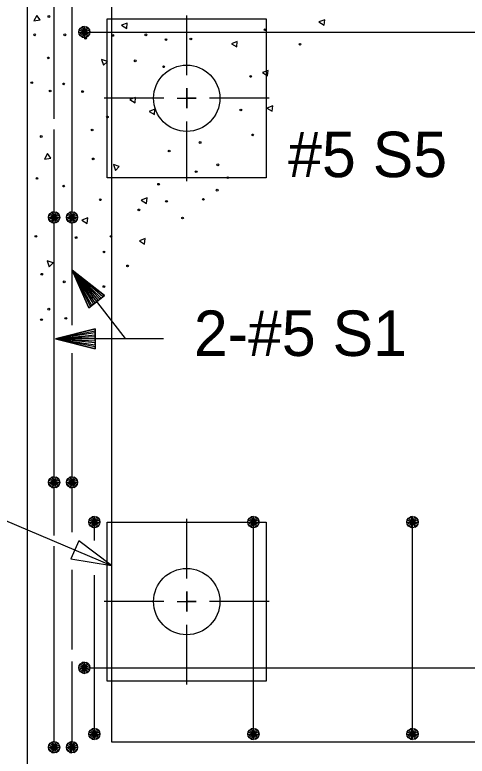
# Model space of a CAD drawing. Extents: x -408 to -23, y -15 to 117.
# Drawn here: x -95.399 to -93.977, y 60.275 to 62.607 of the extents above; entities that cross this region are included whole.
import ezdxf

# ---------------------------------------------------------------- set-up
doc = ezdxf.new("R2010")
doc.units = 0
for name, color, linetype in [('Arrowhead Terminators CELL', 7, 'Continuous'), ('Dimension Lines', 7, 'Continuous'), ('Rebar Lines', 7, 'Continuous'), ('Sup Concrete Girder Lines', 7, 'Continuous'), ('Sup Cored Slab Unit', 7, 'Continuous'), ('Text', 7, 'Continuous'), ('User Information Notes', 7, 'Continuous')]:
    doc.layers.add(name, color=color, linetype=linetype)

msp = doc.modelspace()

# ---------------------------------------------------------------- linework, layer by layer
at = {"layer": 'Arrowhead Terminators CELL'}
msp.add_lwpolyline([(-95.0954, 60.8754), (-95.1983, 60.953), (-95.2227, 60.8954)], close=True, dxfattribs=at)
at = {"layer": 'Dimension Lines'}
for p, q in [((-94.859, 62.4179), (-94.859, 62.6054)), ((-94.9305, 62.3448), (-95.118, 62.3448)), ((-94.5999, 62.3448), (-94.7874, 62.3448)), ((-94.859, 62.0843), (-94.859, 62.2718)), ((-95.0526, 61.5882), (-95.2719, 61.5882)), ((-94.859, 60.8345), (-94.859, 61.022)), ((-94.9305, 60.7615), (-95.118, 60.7615)), ((-94.5999, 60.7615), (-94.7874, 60.7615)), ((-94.859, 60.501), (-94.859, 60.6885))]:
    msp.add_line(p, q, dxfattribs=at)
for points in [[(-94.8889, 62.3448), (-94.859, 62.3448), (-94.8291, 62.3448), (-94.859, 62.3448), (-94.859, 62.3762), (-94.859, 62.3448), (-94.859, 62.3135), (-94.859, 62.3448)], [(-95.2189, 61.8035), (-95.0522, 61.589), (-94.9315, 61.589)], [(-95.1422, 61.7048), (-95.1471, 61.7009), (-95.2189, 61.8035), (-95.152, 61.6971), (-95.157, 61.6933), (-95.2189, 61.8035), (-95.1619, 61.6894), (-95.1668, 61.6856), (-95.2189, 61.8035), (-95.1175, 61.724), (-95.1225, 61.7201), (-95.2189, 61.8035), (-95.1274, 61.7163), (-95.1323, 61.7124), (-95.2189, 61.8035), (-95.1372, 61.7086), (-95.1668, 61.6856), (-95.1175, 61.724), (-95.2189, 61.8035), (-95.1668, 61.6856)], [(-95.1469, 61.5882), (-95.1469, 61.5945), (-95.2719, 61.5882), (-95.1469, 61.6007), (-95.1469, 61.607), (-95.2719, 61.5882), (-95.1469, 61.6132), (-95.1469, 61.6195), (-95.2719, 61.5882), (-95.1469, 61.557), (-95.1469, 61.5632), (-95.2719, 61.5882), (-95.1469, 61.5695), (-95.1469, 61.5757), (-95.2719, 61.5882), (-95.1469, 61.582), (-95.1469, 61.6195), (-95.1469, 61.557), (-95.2719, 61.5882), (-95.1469, 61.6195)], [(-96.0286, 61.1762), (-95.8052, 61.1762), (-95.0954, 60.8754)], [(-94.8889, 60.7615), (-94.859, 60.7615), (-94.8291, 60.7615), (-94.859, 60.7615), (-94.859, 60.7929), (-94.859, 60.7615), (-94.859, 60.7302), (-94.859, 60.7615)]]:
    msp.add_lwpolyline(points, dxfattribs=at)
at = {"layer": 'Rebar Lines'}
for p, q in [((-95.2757, 62.28), (-95.2757, 62.8032)), ((-95.2195, 61.6311), (-95.2195, 62.6541)), ((-95.1806, 62.5532), (-92.5556, 62.5532)), ((-95.2757, 61.43), (-95.2757, 62.2463)), ((-95.2195, 60.9796), (-95.2195, 61.543)), ((-95.2757, 60.9693), (-95.2757, 61.43)), ((-95.1492, 60.9535), (-95.1492, 61.0115)), ((-94.6492, 60.3448), (-94.6492, 61.0115)), ((-94.1492, 60.3448), (-94.1492, 61.0115)), ((-95.2757, 60.3032), (-95.2757, 60.9356)), ((-95.2195, 60.611), (-95.2195, 60.8609)), ((-95.1492, 60.3448), (-95.1492, 60.8443)), ((-95.2195, 60.3032), (-95.2195, 60.5731)), ((-95.1806, 60.5532), (-92.5556, 60.5532))]:
    msp.add_line(p, q, dxfattribs=at)
for points in [[(-93.637, 62.7867), (-95.0954, 62.7867), (-95.0954, 60.3201), (-93.637, 60.3201)], [(-95.1982, 62.5532), (-95.1969, 62.5599), (-95.1931, 62.5656), (-95.1874, 62.5695), (-95.1806, 62.5708), (-95.1739, 62.5695), (-95.1682, 62.5656), (-95.1644, 62.5599), (-95.163, 62.5532), (-95.1644, 62.5465), (-95.1682, 62.5407), (-95.1739, 62.5369), (-95.1806, 62.5355), (-95.1874, 62.5369), (-95.1931, 62.5407), (-95.1969, 62.5464), (-95.1982, 62.5532), (-95.1806, 62.5532), (-95.163, 62.5532), (-95.1644, 62.5599), (-95.1806, 62.5532), (-95.1682, 62.5656), (-95.1739, 62.5695), (-95.1806, 62.5532), (-95.1806, 62.5708), (-95.1874, 62.5695), (-95.1806, 62.5532), (-95.1931, 62.5656), (-95.1969, 62.5599), (-95.1806, 62.5532), (-95.1969, 62.5464), (-95.1931, 62.5407), (-95.1806, 62.5532), (-95.1874, 62.5369), (-95.1806, 62.5355), (-95.1806, 62.5532), (-95.1739, 62.5369), (-95.1682, 62.5407), (-95.1806, 62.5532), (-95.1644, 62.5465)], [(-95.2933, 61.9698), (-95.292, 61.9766), (-95.2882, 61.9823), (-95.2825, 61.9861), (-95.2757, 61.9874), (-95.269, 61.9861), (-95.2632, 61.9823), (-95.2594, 61.9766), (-95.2581, 61.9698), (-95.2594, 61.9631), (-95.2632, 61.9574), (-95.2689, 61.9535), (-95.2757, 61.9522), (-95.2825, 61.9535), (-95.2881, 61.9573), (-95.292, 61.9631), (-95.2933, 61.9698), (-95.2757, 61.9698), (-95.2581, 61.9698), (-95.2594, 61.9766), (-95.2757, 61.9698), (-95.2632, 61.9823), (-95.269, 61.9861), (-95.2757, 61.9698), (-95.2757, 61.9874), (-95.2825, 61.9861), (-95.2757, 61.9698), (-95.2882, 61.9823), (-95.292, 61.9766), (-95.2757, 61.9698), (-95.292, 61.9631), (-95.2881, 61.9573), (-95.2757, 61.9698), (-95.2825, 61.9535), (-95.2757, 61.9522), (-95.2757, 61.9698), (-95.2689, 61.9535), (-95.2632, 61.9574), (-95.2757, 61.9698), (-95.2594, 61.9631)], [(-95.2371, 61.9698), (-95.2358, 61.9766), (-95.232, 61.9823), (-95.2263, 61.9861), (-95.2195, 61.9874), (-95.2128, 61.9861), (-95.2071, 61.9823), (-95.2033, 61.9766), (-95.2019, 61.9698), (-95.2033, 61.9631), (-95.2071, 61.9574), (-95.2128, 61.9535), (-95.2195, 61.9522), (-95.2263, 61.9535), (-95.232, 61.9573), (-95.2358, 61.9631), (-95.2371, 61.9698), (-95.2195, 61.9698), (-95.2019, 61.9698), (-95.2033, 61.9766), (-95.2195, 61.9698), (-95.2071, 61.9823), (-95.2128, 61.9861), (-95.2195, 61.9698), (-95.2195, 61.9874), (-95.2263, 61.9861), (-95.2195, 61.9698), (-95.232, 61.9823), (-95.2358, 61.9766), (-95.2195, 61.9698), (-95.2358, 61.9631), (-95.232, 61.9573), (-95.2195, 61.9698), (-95.2263, 61.9535), (-95.2195, 61.9522), (-95.2195, 61.9698), (-95.2128, 61.9535), (-95.2071, 61.9574), (-95.2195, 61.9698), (-95.2033, 61.9631)], [(-95.2933, 61.1365), (-95.292, 61.1432), (-95.2882, 61.149), (-95.2825, 61.1528), (-95.2757, 61.1541), (-95.269, 61.1528), (-95.2632, 61.149), (-95.2594, 61.1433), (-95.2581, 61.1365), (-95.2594, 61.1298), (-95.2632, 61.1241), (-95.2689, 61.1202), (-95.2757, 61.1189), (-95.2825, 61.1202), (-95.2881, 61.124), (-95.292, 61.1297), (-95.2933, 61.1365), (-95.2757, 61.1365), (-95.2581, 61.1365), (-95.2594, 61.1433), (-95.2757, 61.1365), (-95.2632, 61.149), (-95.269, 61.1528), (-95.2757, 61.1365), (-95.2757, 61.1541), (-95.2825, 61.1528), (-95.2757, 61.1365), (-95.2882, 61.149), (-95.292, 61.1432), (-95.2757, 61.1365), (-95.292, 61.1297), (-95.2881, 61.124), (-95.2757, 61.1365), (-95.2825, 61.1202), (-95.2757, 61.1189), (-95.2757, 61.1365), (-95.2689, 61.1202), (-95.2632, 61.1241), (-95.2757, 61.1365), (-95.2594, 61.1298)], [(-95.2371, 61.1365), (-95.2358, 61.1432), (-95.232, 61.149), (-95.2263, 61.1528), (-95.2195, 61.1541), (-95.2128, 61.1528), (-95.2071, 61.149), (-95.2033, 61.1433), (-95.2019, 61.1365), (-95.2033, 61.1298), (-95.2071, 61.1241), (-95.2128, 61.1202), (-95.2195, 61.1189), (-95.2263, 61.1202), (-95.232, 61.124), (-95.2358, 61.1297), (-95.2371, 61.1365), (-95.2195, 61.1365), (-95.2019, 61.1365), (-95.2033, 61.1433), (-95.2195, 61.1365), (-95.2071, 61.149), (-95.2128, 61.1528), (-95.2195, 61.1365), (-95.2195, 61.1541), (-95.2263, 61.1528), (-95.2195, 61.1365), (-95.232, 61.149), (-95.2358, 61.1432), (-95.2195, 61.1365), (-95.2358, 61.1297), (-95.232, 61.124), (-95.2195, 61.1365), (-95.2263, 61.1202), (-95.2195, 61.1189), (-95.2195, 61.1365), (-95.2128, 61.1202), (-95.2071, 61.1241), (-95.2195, 61.1365), (-95.2033, 61.1298)], [(-95.1668, 61.0115), (-95.1655, 61.0182), (-95.1617, 61.0239), (-95.1559, 61.0278), (-95.1492, 61.0291), (-95.1425, 61.0278), (-95.1367, 61.0239), (-95.1329, 61.0182), (-95.1316, 61.0115), (-95.1329, 61.0047), (-95.1367, 60.999), (-95.1424, 60.9952), (-95.1492, 60.9938), (-95.1559, 60.9952), (-95.1616, 60.999), (-95.1655, 61.0047), (-95.1668, 61.0115), (-95.1492, 61.0115), (-95.1316, 61.0115), (-95.1329, 61.0182), (-95.1492, 61.0115), (-95.1367, 61.0239), (-95.1425, 61.0278), (-95.1492, 61.0115), (-95.1492, 61.0291), (-95.1559, 61.0278), (-95.1492, 61.0115), (-95.1617, 61.0239), (-95.1655, 61.0182), (-95.1492, 61.0115), (-95.1655, 61.0047), (-95.1616, 60.999), (-95.1492, 61.0115), (-95.1559, 60.9952), (-95.1492, 60.9938), (-95.1492, 61.0115), (-95.1424, 60.9952), (-95.1367, 60.999), (-95.1492, 61.0115), (-95.1329, 61.0047)], [(-94.6668, 61.0115), (-94.6655, 61.0182), (-94.6617, 61.0239), (-94.6559, 61.0278), (-94.6492, 61.0291), (-94.6425, 61.0278), (-94.6367, 61.0239), (-94.6329, 61.0182), (-94.6316, 61.0115), (-94.6329, 61.0047), (-94.6367, 60.999), (-94.6424, 60.9952), (-94.6492, 60.9938), (-94.6559, 60.9952), (-94.6616, 60.999), (-94.6655, 61.0047), (-94.6668, 61.0115), (-94.6492, 61.0115), (-94.6316, 61.0115), (-94.6329, 61.0182), (-94.6492, 61.0115), (-94.6367, 61.0239), (-94.6425, 61.0278), (-94.6492, 61.0115), (-94.6492, 61.0291), (-94.6559, 61.0278), (-94.6492, 61.0115), (-94.6617, 61.0239), (-94.6655, 61.0182), (-94.6492, 61.0115), (-94.6655, 61.0047), (-94.6616, 60.999), (-94.6492, 61.0115), (-94.6559, 60.9952), (-94.6492, 60.9938), (-94.6492, 61.0115), (-94.6424, 60.9952), (-94.6367, 60.999), (-94.6492, 61.0115), (-94.6329, 61.0047)], [(-94.1668, 61.0115), (-94.1655, 61.0182), (-94.1617, 61.0239), (-94.1559, 61.0278), (-94.1492, 61.0291), (-94.1425, 61.0278), (-94.1367, 61.0239), (-94.1329, 61.0182), (-94.1316, 61.0115), (-94.1329, 61.0047), (-94.1367, 60.999), (-94.1424, 60.9952), (-94.1492, 60.9938), (-94.1559, 60.9952), (-94.1616, 60.999), (-94.1655, 61.0047), (-94.1668, 61.0115), (-94.1492, 61.0115), (-94.1316, 61.0115), (-94.1329, 61.0182), (-94.1492, 61.0115), (-94.1367, 61.0239), (-94.1425, 61.0278), (-94.1492, 61.0115), (-94.1492, 61.0291), (-94.1559, 61.0278), (-94.1492, 61.0115), (-94.1617, 61.0239), (-94.1655, 61.0182), (-94.1492, 61.0115), (-94.1655, 61.0047), (-94.1616, 60.999), (-94.1492, 61.0115), (-94.1559, 60.9952), (-94.1492, 60.9938), (-94.1492, 61.0115), (-94.1424, 60.9952), (-94.1367, 60.999), (-94.1492, 61.0115), (-94.1329, 61.0047)], [(-95.1982, 60.5532), (-95.1969, 60.5599), (-95.1931, 60.5656), (-95.1874, 60.5695), (-95.1806, 60.5708), (-95.1739, 60.5695), (-95.1682, 60.5656), (-95.1644, 60.5599), (-95.163, 60.5532), (-95.1644, 60.5465), (-95.1682, 60.5407), (-95.1739, 60.5369), (-95.1806, 60.5355), (-95.1874, 60.5369), (-95.1931, 60.5407), (-95.1969, 60.5464), (-95.1982, 60.5532), (-95.1806, 60.5532), (-95.163, 60.5532), (-95.1644, 60.5599), (-95.1806, 60.5532), (-95.1682, 60.5656), (-95.1739, 60.5695), (-95.1806, 60.5532), (-95.1806, 60.5708), (-95.1874, 60.5695), (-95.1806, 60.5532), (-95.1931, 60.5656), (-95.1969, 60.5599), (-95.1806, 60.5532), (-95.1969, 60.5464), (-95.1931, 60.5407), (-95.1806, 60.5532), (-95.1874, 60.5369), (-95.1806, 60.5355), (-95.1806, 60.5532), (-95.1739, 60.5369), (-95.1682, 60.5407), (-95.1806, 60.5532), (-95.1644, 60.5465)], [(-95.1668, 60.3448), (-95.1655, 60.3515), (-95.1617, 60.3572), (-95.1559, 60.3611), (-95.1492, 60.3624), (-95.1425, 60.3611), (-95.1367, 60.3572), (-95.1329, 60.3516), (-95.1316, 60.3448), (-95.1329, 60.3381), (-95.1367, 60.3323), (-95.1424, 60.3285), (-95.1492, 60.3271), (-95.1559, 60.3285), (-95.1616, 60.3323), (-95.1655, 60.338), (-95.1668, 60.3448), (-95.1492, 60.3448), (-95.1316, 60.3448), (-95.1329, 60.3516), (-95.1492, 60.3448), (-95.1367, 60.3572), (-95.1425, 60.3611), (-95.1492, 60.3448), (-95.1492, 60.3624), (-95.1559, 60.3611), (-95.1492, 60.3448), (-95.1617, 60.3572), (-95.1655, 60.3515), (-95.1492, 60.3448), (-95.1655, 60.338), (-95.1616, 60.3323), (-95.1492, 60.3448), (-95.1559, 60.3285), (-95.1492, 60.3271), (-95.1492, 60.3448), (-95.1424, 60.3285), (-95.1367, 60.3323), (-95.1492, 60.3448), (-95.1329, 60.3381)], [(-94.6668, 60.3448), (-94.6655, 60.3515), (-94.6617, 60.3572), (-94.6559, 60.3611), (-94.6492, 60.3624), (-94.6425, 60.3611), (-94.6367, 60.3572), (-94.6329, 60.3516), (-94.6316, 60.3448), (-94.6329, 60.3381), (-94.6367, 60.3323), (-94.6424, 60.3285), (-94.6492, 60.3271), (-94.6559, 60.3285), (-94.6616, 60.3323), (-94.6655, 60.338), (-94.6668, 60.3448), (-94.6492, 60.3448), (-94.6316, 60.3448), (-94.6329, 60.3516), (-94.6492, 60.3448), (-94.6367, 60.3572), (-94.6425, 60.3611), (-94.6492, 60.3448), (-94.6492, 60.3624), (-94.6559, 60.3611), (-94.6492, 60.3448), (-94.6617, 60.3572), (-94.6655, 60.3515), (-94.6492, 60.3448), (-94.6655, 60.338), (-94.6616, 60.3323), (-94.6492, 60.3448), (-94.6559, 60.3285), (-94.6492, 60.3271), (-94.6492, 60.3448), (-94.6424, 60.3285), (-94.6367, 60.3323), (-94.6492, 60.3448), (-94.6329, 60.3381)], [(-94.1668, 60.3448), (-94.1655, 60.3515), (-94.1617, 60.3572), (-94.1559, 60.3611), (-94.1492, 60.3624), (-94.1425, 60.3611), (-94.1367, 60.3572), (-94.1329, 60.3516), (-94.1316, 60.3448), (-94.1329, 60.3381), (-94.1367, 60.3323), (-94.1424, 60.3285), (-94.1492, 60.3271), (-94.1559, 60.3285), (-94.1616, 60.3323), (-94.1655, 60.338), (-94.1668, 60.3448), (-94.1492, 60.3448), (-94.1316, 60.3448), (-94.1329, 60.3516), (-94.1492, 60.3448), (-94.1367, 60.3572), (-94.1425, 60.3611), (-94.1492, 60.3448), (-94.1492, 60.3624), (-94.1559, 60.3611), (-94.1492, 60.3448), (-94.1617, 60.3572), (-94.1655, 60.3515), (-94.1492, 60.3448), (-94.1655, 60.338), (-94.1616, 60.3323), (-94.1492, 60.3448), (-94.1559, 60.3285), (-94.1492, 60.3271), (-94.1492, 60.3448), (-94.1424, 60.3285), (-94.1367, 60.3323), (-94.1492, 60.3448), (-94.1329, 60.3381)], [(-95.2933, 60.3032), (-95.292, 60.3099), (-95.2882, 60.3156), (-95.2825, 60.3195), (-95.2757, 60.3208), (-95.269, 60.3195), (-95.2632, 60.3156), (-95.2594, 60.3099), (-95.2581, 60.3032), (-95.2594, 60.2965), (-95.2632, 60.2907), (-95.2689, 60.2869), (-95.2757, 60.2855), (-95.2825, 60.2869), (-95.2881, 60.2907), (-95.292, 60.2964), (-95.2933, 60.3032), (-95.2757, 60.3032), (-95.2581, 60.3032), (-95.2594, 60.3099), (-95.2757, 60.3032), (-95.2632, 60.3156), (-95.269, 60.3195), (-95.2757, 60.3032), (-95.2757, 60.3208), (-95.2825, 60.3195), (-95.2757, 60.3032), (-95.2882, 60.3156), (-95.292, 60.3099), (-95.2757, 60.3032), (-95.292, 60.2964), (-95.2881, 60.2907), (-95.2757, 60.3032), (-95.2825, 60.2869), (-95.2757, 60.2855), (-95.2757, 60.3032), (-95.2689, 60.2869), (-95.2632, 60.2907), (-95.2757, 60.3032), (-95.2594, 60.2965)], [(-95.2372, 60.3032), (-95.2359, 60.3099), (-95.2321, 60.3156), (-95.2264, 60.3195), (-95.2196, 60.3208), (-95.2129, 60.3195), (-95.2072, 60.3156), (-95.2034, 60.3099), (-95.202, 60.3032), (-95.2034, 60.2965), (-95.2072, 60.2907), (-95.2129, 60.2869), (-95.2196, 60.2855), (-95.2264, 60.2869), (-95.2321, 60.2907), (-95.2359, 60.2964), (-95.2372, 60.3032), (-95.2196, 60.3032), (-95.202, 60.3032), (-95.2034, 60.3099), (-95.2196, 60.3032), (-95.2072, 60.3156), (-95.2129, 60.3195), (-95.2196, 60.3032), (-95.2196, 60.3208), (-95.2264, 60.3195), (-95.2196, 60.3032), (-95.2321, 60.3156), (-95.2359, 60.3099), (-95.2196, 60.3032), (-95.2359, 60.2964), (-95.2321, 60.2907), (-95.2196, 60.3032), (-95.2264, 60.2869), (-95.2196, 60.2855), (-95.2196, 60.3032), (-95.2129, 60.2869), (-95.2072, 60.2907), (-95.2196, 60.3032), (-95.2034, 60.2965)]]:
    msp.add_lwpolyline(points, dxfattribs=at)
at = {"layer": 'Sup Concrete Girder Lines'}
msp.add_line((-95.359, 60.0532), (-95.359, 63.0532), dxfattribs=at)
for points in [[(-95.3198, 62.5914), (-95.3298, 62.6055), (-95.339, 62.5885), (-95.3198, 62.5914)], [(-95.0472, 62.5643), (-95.0457, 62.5815), (-95.0637, 62.5744), (-95.0472, 62.5643)], [(-94.4268, 62.5746), (-94.4253, 62.5918), (-94.4432, 62.5847), (-94.4268, 62.5746)], [(-94.7018, 62.5064), (-94.7003, 62.5235), (-94.7183, 62.5165), (-94.7018, 62.5064)], [(-95.1204, 62.4486), (-95.1081, 62.4608), (-95.1265, 62.4669), (-95.1204, 62.4486)], [(-94.6046, 62.4154), (-94.6031, 62.4325), (-94.6211, 62.4255), (-94.6046, 62.4154)], [(-95.0211, 62.3303), (-95.0196, 62.3475), (-95.0376, 62.3404), (-95.0211, 62.3303)], [(-94.5902, 62.3037), (-94.5887, 62.3209), (-94.6066, 62.3138), (-94.5902, 62.3037)], [(-94.9603, 62.2933), (-94.9588, 62.3105), (-94.9768, 62.3034), (-94.9603, 62.2933)], [(-95.2864, 62.1563), (-95.2964, 62.1705), (-95.3055, 62.1535), (-95.2864, 62.1563)], [(-95.0832, 62.1177), (-95.0709, 62.1299), (-95.0893, 62.136), (-95.0832, 62.1177)], [(-94.9852, 62.0142), (-94.9837, 62.0314), (-95.0016, 62.0243), (-94.9852, 62.0142)], [(-95.1717, 61.951), (-95.1702, 61.9682), (-95.1882, 61.9611), (-95.1717, 61.951)], [(-94.9914, 61.8859), (-94.9899, 61.9031), (-95.0078, 61.896), (-94.9914, 61.8859)], [(-95.2915, 61.8146), (-95.2792, 61.8269), (-95.2976, 61.833), (-95.2915, 61.8146)]]:
    msp.add_lwpolyline(points, dxfattribs=at)
for centre, radius in [((-95.2922, 62.602), 0.00273), ((-94.6123, 62.5602), 0.00273), ((-95.3368, 62.5443), 0.00273), ((-95.242, 62.5443), 0.00273), ((-95.1769, 62.5332), 0.00273), ((-95.0914, 62.5425), 0.00273), ((-94.9873, 62.5443), 0.00273), ((-94.9241, 62.5295), 0.00273), ((-94.846, 62.5313), 0.00273), ((-94.5027, 62.5147), 0.00273), ((-95.294, 62.4718), 0.00273), ((-95.0208, 62.4625), 0.00273), ((-94.859, 62.3448), 0.1042), ((-94.9315, 62.444), 0.00273), ((-94.6578, 62.4134), 0.00273), ((-95.3461, 62.3937), 0.00273), ((-95.2457, 62.39), 0.00273), ((-95.2885, 62.3677), 0.00273), ((-95.1862, 62.3658), 0.00273), ((-94.6888, 62.3079), 0.00273), ((-95.1081, 62.2859), 0.00273), ((-95.1565, 62.245), 0.00273), ((-95.3163, 62.2245), 0.00273), ((-94.6516, 62.2294), 0.00273), ((-94.817, 62.2057), 0.00273), ((-94.9142, 62.1788), 0.00273), ((-95.1528, 62.1539), 0.00273), ((-94.7612, 62.1354), 0.00273), ((-94.8292, 62.1139), 0.00273), ((-95.3294, 62.0925), 0.00273), ((-94.7302, 62.0949), 0.00273), ((-95.2457, 62.0684), 0.00273), ((-94.9473, 62.0743), 0.00273), ((-94.7632, 62.0556), 0.00273), ((-95.1305, 62.0256), 0.00273), ((-94.9225, 62.0205), 0.00273), ((-94.8067, 62.0267), 0.00273), ((-95.0093, 61.9936), 0.00273), ((-94.872, 61.968), 0.00273), ((-95.3331, 61.9103), 0.00273), ((-95.2067, 61.9066), 0.00273), ((-95.097, 61.9103), 0.00273), ((-95.119, 61.8612), 0.00273), ((-95.0449, 61.8174), 0.00273), ((-95.3145, 61.7913), 0.00273), ((-95.2438, 61.7672), 0.00273), ((-95.1193, 61.7523), 0.00273), ((-95.1582, 61.7185), 0.00273), ((-95.2927, 61.6814), 0.00273), ((-95.3154, 61.6482), 0.00273), ((-95.2389, 61.6524), 0.00273), ((-94.859, 60.7615), 0.1042)]:
    msp.add_circle(centre, radius, dxfattribs=at)
at = {"layer": 'Sup Cored Slab Unit'}
for points in [[(-95.109, 62.5948), (-94.609, 62.5948), (-94.609, 62.0948), (-95.109, 62.0948)], [(-95.109, 61.0115), (-94.609, 61.0115), (-94.609, 60.5115), (-95.109, 60.5115)]]:
    msp.add_lwpolyline(points, close=True, dxfattribs=at)
at = {"layer": 'User Information Notes'}
msp.add_line((-95.2195, 60.3032), (-95.2195, 60.3032), dxfattribs=at)

# ---------------------------------------------------------------- texts
at = {"layer": 'Text'}
for s, p in [('#5 S5', (-94.5402, 62.0966)), ('2-#5 S1', (-94.8365, 61.5341))]:
    msp.add_text(s, height=0.14302, dxfattribs=at).set_placement(p)

doc.saveas('drawing.dxf')
